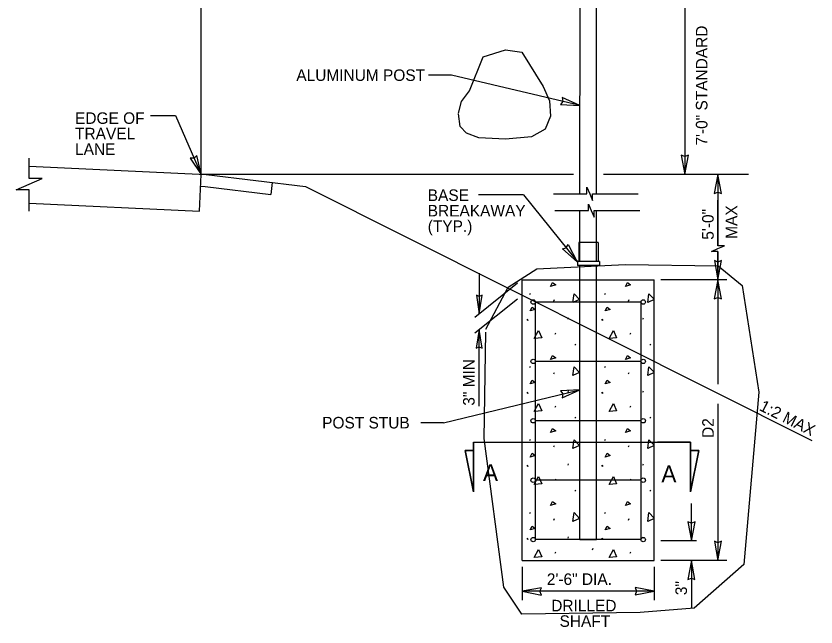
# Model space of a CAD drawing. Extents: x 52649 to 53276, y 9410 to 9805.
# Drawn here: x 52825.3 to 53007.1, y 9553.8 to 9692.7 of the extents above; entities that cross this region are included whole.
import ezdxf

# ---------------------------------------------------------------- set-up
doc = ezdxf.new("R2010")
doc.units = 0
for name, color, linetype in [('1', 7, 'Continuous'), ('2', 7, 'Continuous'), ('43', 7, 'Continuous'), ('52', 7, 'Continuous'), ('57', 7, 'Continuous'), ('58', 7, 'Continuous'), ('62', 7, 'Continuous'), ('DimLines_dp', 7, 'Continuous')]:
    doc.layers.add(name, color=color, linetype=linetype)

msp = doc.modelspace()

# ---------------------------------------------------------------- linework, layer by layer
at = {"layer": '1'}
for p, q in [((52953.49, 9652.28), (52953.51, 9706.73)), ((52957.24, 9652.28), (52957.26, 9706.73)), ((52867.02, 9648.36), (52867.41, 9656.72)), ((52883.55, 9654.84), (52883.22, 9652.14)), ((52953.49, 9641.23), (52953.49, 9648.47)), ((52957.24, 9641.23), (52957.24, 9648.48)), ((52953.22, 9641.23), (52953.22, 9636.92)), ((52957.59, 9641.23), (52953.22, 9641.23)), ((52953.49, 9636.92), (52953.49, 9641.23)), ((52957.24, 9636.92), (52957.24, 9641.23)), ((52957.59, 9641.23), (52957.59, 9636.92)), ((52952.91, 9636.92), (52952.91, 9635.98)), ((52957.91, 9636.91), (52952.91, 9636.91)), ((52957.91, 9635.98), (52952.91, 9635.98)), ((52953.48, 9573.7), (52953.49, 9635.98)), ((52957.23, 9573.7), (52957.24, 9635.98)), ((52957.91, 9636.92), (52957.91, 9635.98)), ((52940.36, 9568.98), (52940.37, 9632.77)), ((52940.37, 9632.77), (52970.37, 9632.76)), ((52970.36, 9568.97), (52970.37, 9632.76)), ((52942.13, 9629.39), (52942.28, 9629.71)), ((52947.53, 9627.93), (52947.68, 9628.25)), ((52959.15, 9629.39), (52959.29, 9629.71)), ((52964.55, 9627.93), (52964.69, 9628.25)), ((52967.36, 9627.7), (52943.36, 9627.7)), ((52943.36, 9573.7), (52943.36, 9627.7)), ((52967.36, 9573.7), (52967.36, 9627.7)), ((52941.39, 9623.81), (52941.53, 9623.6)), ((52941.53, 9623.73), (52941.67, 9623.52)), ((52950.77, 9623.81), (52950.91, 9624.13)), ((52958.4, 9623.81), (52958.55, 9623.6)), ((52958.55, 9623.73), (52958.69, 9623.52)), ((52967.78, 9623.81), (52967.92, 9624.13)), ((52947.89, 9620.36), (52948.03, 9620.68)), ((52964.9, 9620.36), (52965.05, 9620.68)), ((52952.33, 9618.09), (52952.47, 9617.88)), ((52969.34, 9618.09), (52969.49, 9617.88)), ((52967.36, 9614.2), (52943.36, 9614.2)), ((52942.13, 9612.8), (52942.28, 9613.12)), ((52959.15, 9612.8), (52959.29, 9613.12)), ((52947.53, 9611.34), (52947.68, 9611.66)), ((52964.55, 9611.34), (52964.69, 9611.66)), ((52941.39, 9607.22), (52941.53, 9607.01)), ((52941.53, 9607.14), (52941.67, 9606.92)), ((52950.77, 9607.22), (52950.91, 9607.54)), ((52958.4, 9607.22), (52958.55, 9607.01)), ((52958.55, 9607.14), (52958.69, 9606.92)), ((52967.78, 9607.22), (52967.92, 9607.54)), ((52947.89, 9603.77), (52948.03, 9604.09)), ((52964.9, 9603.77), (52965.05, 9604.09)), ((52952.33, 9601.5), (52952.47, 9601.28)), ((52969.34, 9601.5), (52969.49, 9601.28)), ((52967.36, 9600.7), (52943.36, 9600.7)), ((52942.13, 9596.2), (52942.28, 9596.52)), ((52959.15, 9596.2), (52959.29, 9596.52)), ((52947.53, 9594.75), (52947.68, 9595.07)), ((52964.55, 9594.75), (52964.69, 9595.07)), ((52941.39, 9590.63), (52941.53, 9590.41)), ((52941.53, 9590.55), (52941.67, 9590.33)), ((52950.77, 9590.63), (52950.91, 9590.95)), ((52958.4, 9590.63), (52958.55, 9590.41)), ((52958.55, 9590.55), (52958.69, 9590.33)), ((52967.78, 9590.63), (52967.92, 9590.95)), ((52967.36, 9587.2), (52943.36, 9587.2)), ((52947.89, 9587.18), (52948.03, 9587.5)), ((52964.9, 9587.18), (52965.05, 9587.5)), ((52952.33, 9584.9), (52952.47, 9584.69)), ((52969.34, 9584.9), (52969.49, 9584.69)), ((52942.13, 9579.61), (52942.28, 9579.93)), ((52959.15, 9579.61), (52959.29, 9579.93)), ((52947.53, 9578.15), (52947.68, 9578.47)), ((52964.55, 9578.15), (52964.69, 9578.47)), ((52941.39, 9574.03), (52941.53, 9573.82)), ((52941.53, 9573.95), (52941.67, 9573.74)), ((52967.36, 9573.7), (52943.36, 9573.7)), ((52950.77, 9574.03), (52950.91, 9574.35)), ((52953.48, 9573.7), (52957.23, 9573.71)), ((52958.4, 9574.03), (52958.55, 9573.82)), ((52958.55, 9573.95), (52958.69, 9573.74)), ((52967.78, 9574.03), (52967.92, 9574.35)), ((52947.89, 9570.58), (52948.03, 9570.9)), ((52956.31, 9571.4), (52956.45, 9571.72)), ((52964.9, 9570.58), (52965.05, 9570.9)), ((52940.36, 9568.98), (52970.36, 9568.97))]:
    msp.add_line(p, q, dxfattribs=at)
for points in [[(52828.33, 9658.57), (52868.59, 9656.66), (52891.09, 9653.92)], [(52867.29, 9654), (52868.36, 9653.95), (52883.22, 9652.14)], [(52891.09, 9653.92), (53006.17, 9596.19)], [(52828.33, 9650.19), (52867.02, 9648.36)], [(52946.83, 9631.22), (52947.26, 9632.11), (52947.97, 9631.57), (52946.83, 9631.22)], [(52963.84, 9631.22), (52964.27, 9632.11), (52964.98, 9631.57), (52963.84, 9631.22)], [(52951.85, 9627.56), (52952.14, 9629.59), (52953.41, 9628.28), (52951.89, 9627.58)], [(52968.87, 9627.56), (52969.15, 9629.59), (52970.37, 9628.34)], [(52970.37, 9628.25), (52968.9, 9627.58)], [(52942.21, 9625.66), (52942.63, 9626.55), (52943.34, 9626.01), (52942.21, 9625.66)], [(52959.22, 9625.66), (52959.65, 9626.55), (52960.36, 9626.01), (52959.22, 9625.66)], [(52943.09, 9619.4), (52944.05, 9621.21), (52944.8, 9619.54), (52943.13, 9619.4)], [(52960.11, 9619.4), (52961.07, 9621.21), (52961.81, 9619.54), (52960.14, 9619.4)], [(52946.83, 9614.63), (52947.26, 9615.51), (52947.97, 9614.98), (52946.83, 9614.63)], [(52963.84, 9614.63), (52964.27, 9615.51), (52964.98, 9614.98), (52963.84, 9614.63)], [(52951.85, 9610.97), (52952.14, 9613), (52953.41, 9611.69), (52951.89, 9610.98)], [(52968.87, 9610.97), (52969.15, 9613), (52970.36, 9611.75)], [(52970.36, 9611.66), (52968.9, 9610.98)], [(52942.21, 9609.07), (52942.63, 9609.95), (52943.34, 9609.42), (52942.21, 9609.07)], [(52959.22, 9609.07), (52959.65, 9609.95), (52960.36, 9609.42), (52959.22, 9609.07)], [(52943.09, 9602.81), (52944.05, 9604.62), (52944.8, 9602.95), (52943.13, 9602.81)], [(52960.11, 9602.81), (52961.07, 9604.62), (52961.81, 9602.95), (52960.14, 9602.81)], [(52946.83, 9598.03), (52947.26, 9598.92), (52947.97, 9598.39), (52946.83, 9598.03)], [(52963.84, 9598.03), (52964.27, 9598.92), (52964.98, 9598.39), (52963.84, 9598.03)], [(52951.85, 9594.38), (52952.14, 9596.41), (52953.41, 9595.1), (52951.89, 9594.39)], [(52968.87, 9594.38), (52969.15, 9596.41), (52970.36, 9595.16)], [(52970.36, 9595.07), (52968.9, 9594.39)], [(52942.21, 9592.47), (52942.63, 9593.36), (52943.34, 9592.83), (52942.21, 9592.47)], [(52959.22, 9592.47), (52959.65, 9593.36), (52960.36, 9592.83), (52959.22, 9592.47)], [(52943.09, 9586.22), (52944.05, 9588.03), (52944.8, 9586.36), (52943.13, 9586.22)], [(52960.11, 9586.22), (52961.07, 9588.03), (52961.81, 9586.36), (52960.14, 9586.22)], [(52946.83, 9581.44), (52947.26, 9582.33), (52947.97, 9581.8), (52946.83, 9581.44)], [(52963.84, 9581.44), (52964.27, 9582.33), (52964.98, 9581.8), (52963.84, 9581.44)], [(52951.85, 9577.79), (52952.14, 9579.82), (52953.41, 9578.5), (52951.89, 9577.8)], [(52968.87, 9577.79), (52969.15, 9579.82), (52970.36, 9578.57)], [(52970.36, 9578.47), (52968.9, 9577.8)], [(52942.21, 9575.88), (52942.63, 9576.77), (52943.34, 9576.24), (52942.21, 9575.88)], [(52959.22, 9575.88), (52959.65, 9576.77), (52960.36, 9576.24), (52959.22, 9575.88)], [(52943.09, 9569.62), (52944.05, 9571.44), (52944.8, 9569.77), (52943.13, 9569.62)], [(52960.11, 9569.62), (52961.07, 9571.44), (52961.81, 9569.77), (52960.14, 9569.62)]]:
    msp.add_lwpolyline(points, dxfattribs=at)
for centre in [(52942.86, 9627.7), (52967.86, 9627.7), (52942.86, 9614.2), (52967.86, 9614.2), (52942.86, 9600.7), (52967.86, 9600.7), (52942.86, 9587.2), (52967.86, 9587.2), (52942.86, 9573.7), (52967.86, 9573.7)]:
    msp.add_circle(centre, 0.5, dxfattribs=at)
at = {"layer": '2'}
for points in [[(52929.29, 9593.95), (52927.41, 9593.95), (52929.29, 9584.58)], [(52980.51, 9593.95), (52978.63, 9584.58), (52978.63, 9593.95)]]:
    msp.add_lwpolyline(points, close=True, dxfattribs=at)
at = {"layer": '43'}
for p, q in [((52947.49, 9652.27), (52955.07, 9652.27)), ((52957.59, 9652.28), (52966.74, 9652.28)), ((52947.81, 9648.47), (52955.4, 9648.47)), ((52957.91, 9648.48), (52967.07, 9648.48))]:
    msp.add_line(p, q, dxfattribs=at)
for points in [[(52828.33, 9648.33), (52828.33, 9653.19), (52825.35, 9653.19), (52828.33, 9654.49), (52831.3, 9655.78), (52828.33, 9655.78), (52828.33, 9660.39)], [(52953.68, 9652.28), (52955.07, 9652.28), (52955.07, 9653.77), (52955.72, 9652.28), (52956.37, 9650.79), (52956.37, 9652.28), (52957.76, 9652.28)], [(52954.01, 9648.48), (52955.4, 9648.48), (52955.4, 9649.97), (52956.05, 9648.48), (52956.69, 9646.99), (52956.69, 9648.48), (52958.09, 9648.48)]]:
    msp.add_lwpolyline(points, dxfattribs=at)
at = {"layer": '52'}
for p, q in [((52952.02, 9656.72), (52867.42, 9656.72)), ((52940.37, 9629.2), (52940.37, 9632.77)), ((52979.97, 9573.42), (52971.86, 9573.42))]:
    msp.add_line(p, q, dxfattribs=at)
at = {"layer": '58'}
for p, q in [((52929.29, 9595.83), (52929.29, 9584.58)), ((52929.29, 9593.95), (52929.29, 9595.83)), ((52929.29, 9595.83), (52936.79, 9595.83)), ((52935.22, 9595.83), (52978.63, 9595.83)), ((52978.63, 9595.83), (52971.13, 9595.83)), ((52978.63, 9595.83), (52978.63, 9584.58)), ((52978.63, 9593.95), (52978.63, 9595.83)), ((52929.29, 9584.58), (52927.41, 9593.95)), ((52927.41, 9593.95), (52929.29, 9593.95)), ((52978.63, 9584.58), (52980.51, 9593.95)), ((52980.51, 9593.95), (52978.63, 9593.95))]:
    msp.add_line(p, q, dxfattribs=at)
at = {"layer": '62'}
msp.add_lwpolyline([(52925.88, 9670.66), (52926.58, 9673.26), (52928.38, 9675.67), (52931.48, 9683.42), (52936.59, 9685.02), (52940.29, 9684.52), (52945.09, 9676.67), (52946.59, 9673.46), (52946.79, 9669.96), (52945.59, 9666.96), (52942.49, 9665.25), (52936.59, 9664.75), (52930.48, 9665.05), (52927.68, 9666.05), (52926.28, 9667.56), (52925.88, 9670.46)], dxfattribs=at)
at = {"layer": 'DimLines_dp'}
for p, q in [((52867.42, 9656.72), (52867.42, 9768.2)), ((52977.32, 9706.73), (52977.32, 9656.72)), ((52924.28, 9679.27), (52919.1, 9679.27)), ((52953.5, 9672.35), (52924.28, 9679.27)), ((52953.49, 9672.35), (52949.46, 9674.17)), ((52949.46, 9674.17), (52949.58, 9673.27)), ((52949.58, 9673.27), (52949.08, 9672.56)), ((52949.08, 9672.56), (52953.49, 9672.35)), ((52855.94, 9670.1), (52861.59, 9670.1)), ((52861.59, 9670.1), (52867.41, 9656.72)), ((52866.45, 9661.04), (52865.81, 9660.4)), ((52867.41, 9656.72), (52866.45, 9661.04)), ((52977.32, 9660.74), (52976.51, 9661.07)), ((52976.51, 9661.07), (52977.32, 9656.72)), ((52977.32, 9656.72), (52978.16, 9661.07)), ((52978.16, 9661.07), (52977.32, 9660.74)), ((52865.81, 9660.4), (52864.94, 9660.38)), ((52864.94, 9660.38), (52867.41, 9656.72)), ((52991.78, 9656.72), (52958.83, 9656.72)), ((52984.83, 9656.72), (52983.99, 9652.37)), ((52985.64, 9652.37), (52984.83, 9656.72)), ((52984.83, 9656.72), (52984.83, 9640.5)), ((52940.67, 9652.09), (52930.44, 9652.09)), ((52940.67, 9652.09), (52952.91, 9636.83)), ((52983.99, 9652.37), (52984.83, 9652.7)), ((52984.83, 9652.7), (52985.64, 9652.37)), ((52984.83, 9641.72), (52984.83, 9650.88)), ((52949.51, 9639.79), (52950.38, 9640.05)), ((52952.83, 9636.86), (52949.51, 9639.79)), ((52950.38, 9640.05), (52950.82, 9640.8)), ((52950.82, 9640.8), (52952.83, 9636.86)), ((52984.83, 9639.21), (52984.83, 9632.76)), ((52984.85, 9631.62), (52984.85, 9639.21)), ((52984.83, 9636.78), (52984.02, 9637.11)), ((52984.02, 9637.11), (52984.83, 9632.76)), ((52984.83, 9632.76), (52985.67, 9637.11)), ((52985.67, 9637.11), (52984.83, 9636.78)), ((52930.6, 9634.25), (52930.6, 9625.03)), ((52939.33, 9631.95), (52929.57, 9624.21)), ((52986.83, 9632.76), (52971.87, 9632.76)), ((52984.83, 9632.76), (52983.99, 9628.41)), ((52985.64, 9628.41), (52984.83, 9632.76)), ((52984.83, 9632.76), (52984.83, 9609.02)), ((52939.33, 9628.38), (52929.57, 9620.65)), ((52930.6, 9628.95), (52929.96, 9629.27)), ((52929.96, 9629.27), (52930.6, 9625.03)), ((52930.6, 9625.03), (52931.27, 9629.27)), ((52931.27, 9629.27), (52930.6, 9628.95)), ((52983.99, 9628.41), (52984.83, 9628.74)), ((52984.83, 9628.74), (52985.64, 9628.41)), ((52930.6, 9621.46), (52929.93, 9617.22)), ((52930.6, 9603.99), (52930.6, 9621.46)), ((52931.25, 9617.22), (52930.6, 9621.46)), ((52929.93, 9617.22), (52930.6, 9617.54)), ((52930.6, 9617.54), (52931.25, 9617.22)), ((52922.51, 9600.25), (52953.48, 9607.75)), ((52953.48, 9607.75), (52949.06, 9607.54)), ((52949.06, 9607.54), (52949.58, 9606.8)), ((52949.45, 9605.94), (52953.48, 9607.75)), ((52949.58, 9606.8), (52949.45, 9605.94)), ((52984.83, 9604.56), (52984.83, 9568.97)), ((52922.51, 9600.25), (52917.34, 9600.25)), ((52978.81, 9573.42), (52978.81, 9581.89)), ((52978.81, 9577.44), (52978, 9577.77)), ((52978, 9577.77), (52978.81, 9573.42)), ((52978.81, 9573.42), (52979.65, 9577.77)), ((52979.65, 9577.77), (52978.81, 9577.44)), ((52984.83, 9572.99), (52984.02, 9573.32)), ((52984.02, 9573.32), (52984.83, 9568.97)), ((52984.83, 9568.97), (52985.67, 9573.32)), ((52985.67, 9573.32), (52984.83, 9572.99)), ((52986.83, 9568.97), (52971.86, 9568.97)), ((52978.81, 9568.97), (52977.97, 9564.62)), ((52978.81, 9568.97), (52978.81, 9558.26)), ((52979.62, 9564.62), (52978.81, 9568.97)), ((52940.36, 9567.47), (52940.36, 9559.94)), ((52970.36, 9567.47), (52970.36, 9559.94)), ((52977.97, 9564.62), (52978.81, 9564.95)), ((52978.81, 9564.95), (52979.62, 9564.62)), ((52944.71, 9562.75), (52940.36, 9561.94)), ((52944.38, 9561.94), (52944.71, 9562.75)), ((52970.36, 9561.94), (52966.01, 9562.78)), ((52966.01, 9562.78), (52966.34, 9561.94)), ((52970.36, 9561.94), (52940.36, 9561.94)), ((52940.36, 9561.94), (52944.71, 9561.1)), ((52944.71, 9561.1), (52944.38, 9561.94)), ((52966.34, 9561.94), (52966.01, 9561.13)), ((52966.01, 9561.13), (52970.36, 9561.94))]:
    msp.add_line(p, q, dxfattribs=at)
for points in [[(52984.84, 9637.82), (52984.83, 9639.21), (52983.35, 9639.21), (52984.83, 9639.86), (52986.32, 9640.5), (52984.83, 9640.5), (52984.83, 9641.89)], [(52932.09, 9621.56), (52937.2, 9631.11), (52943.68, 9635.21), (52963.79, 9636.23), (52984.92, 9635.89), (52990.37, 9631.46), (52994.12, 9607.24), (52990.71, 9568.01), (52979.47, 9558.12), (52967.2, 9557.1), (52940.27, 9556.76), (52936.18, 9562.9), (52931.75, 9596.66), (52932.09, 9620.88)]]:
    msp.add_lwpolyline(points, dxfattribs=at)

# ---------------------------------------------------------------- texts
at = {"layer": '52'}
msp.add_text('1:2 MAX', height=2.625, rotation=333.3603, dxfattribs=at).set_placement((52994.04, 9603.19))
at = {"layer": '57'}
for p in [(52931.45, 9586.99), (52971.98, 9586.71)]:
    msp.add_text('A', height=3.84, dxfattribs=at).set_placement(p)
at = {"layer": 'DimLines_dp'}
for s, p in [('7\'-0" STANDARD', (52982.45, 9663.26)), ('5\'-0"', (52983.87, 9641.86)), ('MAX', (52989.21, 9642.07)), ('3" MIN', (52929.55, 9604.13)), ('D2', (52983.89, 9596.8)), ('3"', (52977.8, 9561.07))]:
    msp.add_text(s, height=2.625, rotation=90, dxfattribs=at).set_placement(p)
for s, p in [('ALUMINUM POST', (52889.04, 9677.95)), ('EDGE OF ', (52838.77, 9668.19)), ('TRAVEL ', (52838.77, 9664.67)), ('LANE', (52838.77, 9661.15)), ('BASE ', (52918.9, 9650.67)), ('BREAKAWAY', (52918.9, 9647.15)), ('(TYP.)', (52918.9, 9643.63)), ('POST STUB', (52894.91, 9598.96)), ('2\'-6" DIA.', (52945.96, 9563.39)), ('DRILLED', (52946.96, 9557.38)), ('SHAFT', (52948.85, 9553.86))]:
    msp.add_text(s, height=2.625, dxfattribs=at).set_placement(p)

doc.saveas('drawing.dxf')
